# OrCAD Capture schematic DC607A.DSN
size Custom; title: LTC3722EGN-1, 36-72Vin to 12V/35A Isolated Supply; rev: A; company: LINEAR TECHNOLOGY; note: DC607A
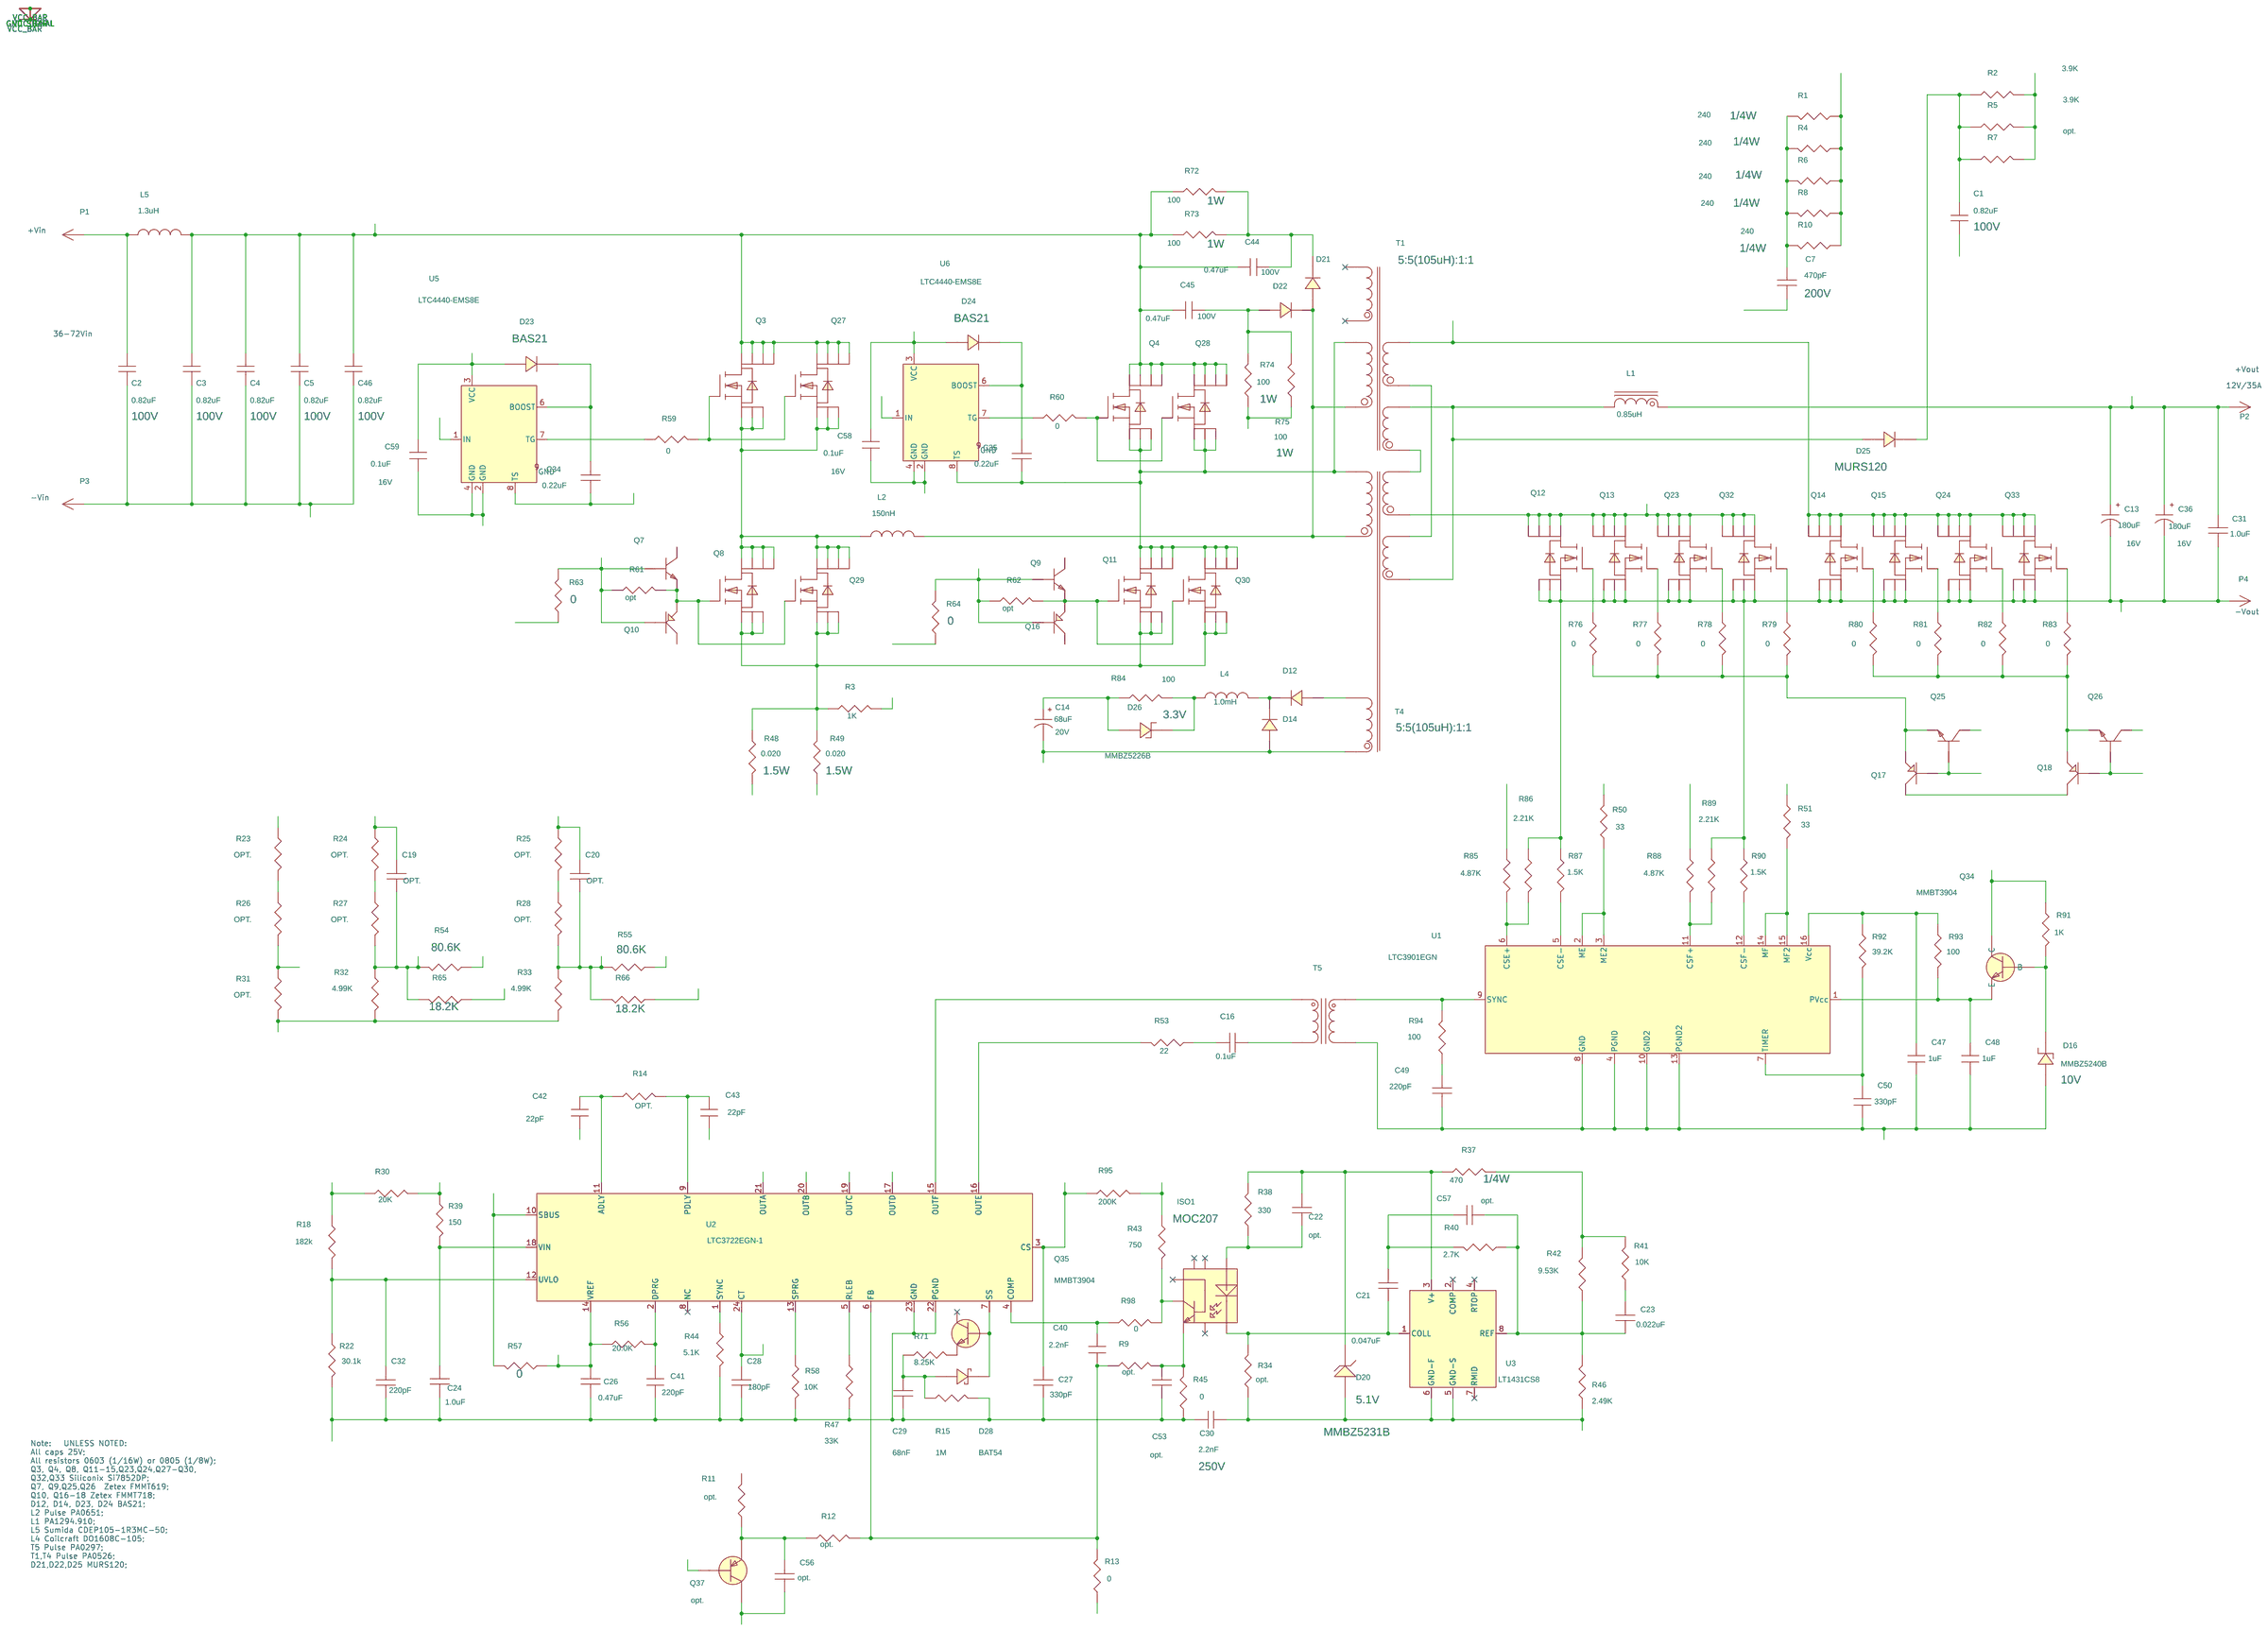
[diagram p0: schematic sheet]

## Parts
C1  0.82uF  [1812]
C2  0.82uF  [1812]
C3  0.82uF  [1812]
C4  0.82uF  [1812]
C5  0.82uF  [1812]
C7  470pF  [CAP1206]
C13  180uF  [CAP-OS-CON-E]
C14  68uF  [CAP7343]
C16  0.1uF  [CAP0805]
C19  OPT.  [CAP0805]
C20  OPT.  [CAP0805]
C21  0.047uF  [CAP0805]
C22  opt.  [CAP0805]
C23  0.022uF  [CAP0805]
C24  1.0uF  [CAP1206]
C26  0.47uF  [CAP1206]
C27  330pF  [CAP0805]
C28  180pF  [CAP0805]
C29  68nF  [CAP0805]
C30  2.2nF  [CAP-KH220]
C31  1.0uF  [CAP1206]
C32  220pF  [CAP0805]
C34  0.22uF  [CAP0805]
C35  0.22uF  [CAP0805]
C36  180uF  [CAP-OS-CON-E]
C40  2.2nF  [CAP0603]
C41  220pF  [CAP0603]
C42  22pF  [CAP0603]
C43  22pF  [CAP0603]
C44  0.47uF  [CAP1210]
C45  0.47uF  [CAP1210]
C46  0.82uF  [1812]
C47  1uF  [CAP0603]
C48  1uF  [CAP0603]
C49  220pF  [CAP0805]
C50  330pF  [CAP0603]
C53  opt.  [CAP0805]
C56  opt.  [CAP0805]
C57  opt.  [CAP0805]
C58  0.1uF  [CAP0603]
C59  0.1uF  [CAP0603]
D12  BAS21  [SOT23DIODE]
D14  BAS21  [SOT23DIODE]
D16  MMBZ5240B  [SOT23]
D20  MMBZ5231B  [SOT23DIODE]
D21  MBRS120T3  [SMB]
D22  MBRS120T3  [SMB]
D23  BAS21  [SOT23DIODE]
D24  BAS21  [SOT23DIODE]
D25  ES1G  [SMB]
D26  MMBZ5226B  [SOT23]
D28  BAT54  [SOT23]
ISO1  MOC207  [so8nb]
L1  0.85uH  [IND-PA1294/1494]
L2  150nH  [KM2T16AWG55041]
L4  1.0mH  [DO1608C]
L5  1.3uH  [IND-CDEP105]
P1  1455-2  [KEYSTONE-1455-2]
P2  1455-2  [KEYSTONE-1455-2]
P3  1455-2  [KEYSTONE-1455-2]
P4  1455-2  [KEYSTONE-1455-2]
Q3  Si7852DP  [POWERPAK-SO-8]
Q4  Si7852DP  [POWERPAK-SO-8]
Q7  FMMT619  [SOT23TRANS]
Q8  Si7852DP  [POWERPAK-SO-8]
Q9  FMMT619  [SOT23TRANS]
Q10  FMMT718  [SOT23TRANS]
Q11  Si7852DP  [POWERPAK-SO-8]
Q12  SI7456DP  [POWERPAK-SO-8]
Q13  SI7456DP  [POWERPAK-SO-8]
Q14  SI7456DP  [POWERPAK-SO-8]
Q15  SI7456DP  [POWERPAK-SO-8]
Q16  FMMT718  [SOT23TRANS]
Q17  FMMT718  [SOT23TRANS]
Q18  FMMT718  [SOT23TRANS]
Q23  SI7456DP  [POWERPAK-SO-8]
Q24  SI7456DP  [POWERPAK-SO-8]
Q25  FMMT619  [SOT23TRANS]
Q26  FMMT619  [SOT23TRANS]
Q27  Si7852DP  [POWERPAK-SO-8]
Q28  Si7852DP  [POWERPAK-SO-8]
Q29  Si7852DP  [POWERPAK-SO-8]
Q30  Si7852DP  [POWERPAK-SO-8]
Q32  (opt.)  [POWERPAK-SO-8]
Q33  (opt.)  [POWERPAK-SO-8]
Q34  MMBT3904  [SOT23]
Q35  MMBT3904  [SOT23]
Q37  opt.  [SOT23]
R1  240  [RES1206]
R2  3.9K  [RES1206]
R3  1K  [RES0603]
R4  240  [RES1206]
R5  3.9K  [RES1206]
R6  240  [RES1206]
R7  opt.  [RES1206]
R8  240  [RES1206]
R9  opt.  [RES0603]
R10  240  [RES1206]
R11  opt.  [RES0603]
R12  opt.  [RES0603]
R13  0  [RES0603]
R14  OPT.  [RES0603]
R15  1M  [RES0603]
R18  182k  [RES0805]
R22  30.1k  [RES0805]
R23  OPT.  [RES0805]
R24  OPT.  [RES0805]
R25  OPT.  [RES0805]
R26  OPT.  [RES0805]
R27  OPT.  [RES0805]
R28  OPT.  [RES0805]
R30  20K  [RES0805]
R31  OPT.  [RES0603]
R32  4.99K  [RES0603]
R33  4.99K  [RES0603]
R34  opt.  [RES0805]
R37  470  [RES1206]
R38  330  [RES0805]
R39  150  [RES0805]
R40  2.7K  [RES0805]
R41  10K  [RES0805]
R42  9.53K  [RES0805]
R43  750  [RES0603]
R44  5.1K  [RES0603]
R45  0  [RES0805]
R46  2.49K  [RES0805]
R47  33K  [RES0603]
R48  0.020  [2512]
R49  0.020  [2512]
R50  33  [RES0805]
R51  33  [RES0805]
R53  22  [RES0805]
R54  80.6K  [RES0603]
R55  80.6K  [RES0603]
R56  20.0K  [RES0603]
R57  0  [RES0603]
R58  10K  [RES0603]
R59  0  [RES0603]
R60  0  [RES0603]
R61  opt  [RES0603]
R62  opt  [RES0603]
R63  0  [RES0603]
R64  0  [RES0603]
R65  18.2K  [RES0603]
R66  18.2K  [RES0603]
R71  8.25K  [RES0603]
R72  100  [RES-LR2512]
R73  100  [RES-LR2512]
R74  100  [RES-LR2512]
R75  100  [RES-LR2512]
R76  0  [RES0603]
R77  0  [RES0603]
R78  0  [RES0603]
R79  0  [RES0603]
R80  0  [RES0603]
R81  0  [RES0603]
R82  0  [RES0603]
R83  0  [RES0603]
R84  100  [RES1206]
R85  4.87K  [RES1206]
R86  2.21K  [RES0603]
R87  1.5K  [RES0603]
R88  4.87K  [RES1206]
R89  2.21K  [RES0603]
R90  1.5K  [RES0603]
R91  1K  [RES0603]
R92  39.2K  [RES0603]
R93  100  [RES0603]
R94  100  [RES0805]
R95  200K  [RES0603]
R98  0  [RES0603]
T1  5:5(105uH):1:1  [TRANS-PA0526]
T4  5:5(105uH):1:1  [TRANS-PA0526]
T5  PA0297  [TRANS-PA0297]
U1  LTC3901EGN  [SSOP-16GN]
U2  LTC3722EGN-1  [SSOP-24GN]
U3  LT1431CS8  [SO-08]
U5  LTC4440-EMS8E  [msop08/cp]
U6  LTC4440-EMS8E  [msop08/cp]

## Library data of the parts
C1-C5 C46 = VJ1825Y155MXB: 1ST PART FIELD: 100V; 2ND PART FIELD: 20%, 1812; 3RD PART FIELD: X7R; 4TH PART FIELD: VITRAMON; 5TH PART FIELD: VJ1812Y824KXBAT; 7TH PART FIELD: CAP.
C7 = 12061C104KAT2A_0: 1ST PART FIELD: 200V; 2ND PART FIELD: 10%, 1206; 3RD PART FIELD: NPO; 4TH PART FIELD: AVX; 5TH PART FIELD: 12062A471KAT2A; 7TH PART FIELD: CAP.
C13 C36 = CAP-OS-CON-E: 1ST PART FIELD: 16V
C14 = CAP+7343: 1ST PART FIELD: 20V
C16 C21 C22 C34 C35 C49 C57 = 12061C104KAT2A_0: 1ST PART FIELD: 25V; 2ND PART FIELD: 10%, 0805; 3RD PART FIELD: X7R; 4TH PART FIELD: AVX; 5TH PART FIELD: 08053C104KAT2A; 7TH PART FIELD: CAP.
C19 C20 = 12061C104KAT2A_0: 1ST PART FIELD: 100V; 2ND PART FIELD: 10%, 0805; 3RD PART FIELD: NPO; 4TH PART FIELD: AVX; 5TH PART FIELD: 08052A4R7KAT2A; 7TH PART FIELD: CAP.
C23 = 12061C104KAT2A_0: 1ST PART FIELD: 25V; 2ND PART FIELD: 10%, 0805; 3RD PART FIELD: X7R; 4TH PART FIELD: AVX; 5TH PART FIELD: 08053C223KAT2A; 7TH PART FIELD: CAP.
C24 C26 C31 = TMK316BJ105KL: 1ST PART FIELD: 25V; 2ND PART FIELD: 10%, 1206; 3RD PART FIELD: X7R; 4TH PART FIELD: TAIYO TUDEN; 7TH PART FIELD: CAP.
C27 C53 = 12061C104KAT2A_0: 1ST PART FIELD: 25V; 2ND PART FIELD: 10%, 0805; 3RD PART FIELD: NPO; 4TH PART FIELD: AVX; 5TH PART FIELD: 08053A331KAT2A; 7TH PART FIELD: CAP.
C28 C56 = 12061C104KAT2A_0: 1ST PART FIELD: 25V; 2ND PART FIELD: 10%, 0805; 3RD PART FIELD: NPO; 4TH PART FIELD: AVX; 5TH PART FIELD: 08053A151KAT2A; 7TH PART FIELD: CAP.
C29 = 12061C104KAT2A_0: 1ST PART FIELD: 25V; 2ND PART FIELD: 10%, 0805; 3RD PART FIELD: X7R; 4TH PART FIELD: AVX; 5TH PART FIELD: 08053C683KAT2A; 7TH PART FIELD: CAP.
C30 = GHM3045X7R222K-GC: 1ST PART FIELD: 250V; 2ND PART FIELD: 10%, GHM3045; 3RD PART FIELD: X7R; 4TH PART FIELD: MURATA ERIE; 7TH PART FIELD: CAP.
C32 = 12061C104KAT2A_0: 1ST PART FIELD: 25V; 2ND PART FIELD: 10%, 0805; 3RD PART FIELD: NPO; 4TH PART FIELD: AVX; 5TH PART FIELD: 08053A101KAT2A; 7TH PART FIELD: CAP.
C40-C43 C47 C48 C50 = CAP0603
C44 C45 = CAP1210: 1ST PART FIELD: 100V
C58 C59 = CAP0603: 1ST PART FIELD: 16V
D12 D14 D23 D24 = BAS21LT1: 1ST PART FIELD: 200V; 2ND PART FIELD: SOT23; 3RD PART FIELD: FAST SWITCHING; 4TH PART FIELD: DIODES INC.; 7TH PART FIELD: DIODE
D16 = MMBZ5221B-5259B: V: 10V
D20 = MMBZ5248BLT1_0: 1ST PART FIELD: 5.1V; 2ND PART FIELD: 5%, SOT23; 3RD PART FIELD: ZENER; 4TH PART FIELD: DIODES INC.; 5TH PART FIELD: MMBZ5240B-7; 7TH PART FIELD: DIODE
D21 D22 = MBRS120T3: 1ST PART FIELD: 200V; 3RD PART FIELD: SUPER FAST; 4TH PART FIELD: DIODES INC.; 5TH PART FIELD: MBRS120
D25 = MBRS120T3: 1ST PART FIELD: 200V; 3RD PART FIELD: SUPER FAST; 4TH PART FIELD: DIODES INC.; 5TH PART FIELD: MURS120
D26 = MMBZ5221B-5259B: v: 3.3V
D28 = BAT54
ISO1 = MOC207: 1ST PART FIELD: 3000VAC; 2ND PART FIELD: SO8; 3RD PART FIELD: OPTOISOLATOR; 4TH PART FIELD: FAIRCHILD SEMI.; 7TH PART FIELD: I.C.
L1 = IND-PA1494-PULSE_3
L2 = DO1608C-105: 3RD PART FIELD: POWDER TORROID; 4TH PART FIELD: PULSE; 5TH PART FIELD: PA0573 (8T19AWGT44-2); 7TH PART FIELD: INDUCTOR
L4 = DO1608C-105: 3RD PART FIELD: FERRITE DRUM; 4TH PART FIELD: COILCRAFT; 7TH PART FIELD: INDUCTOR
L5 = DO1608C-105: 3RD PART FIELD: FERRITE; 4TH PART FIELD: SUMIDA; 5TH PART FIELD: CDEP105-1R3MC-50; 7TH PART FIELD: INDUCTOR
P1-P4 = Keystone-1455-2: 3RD PART FIELD: PIN 0.08 SWAGE MOUNT; 4TH PART FIELD: KEYSTONE; 7TH PART FIELD: CONNECTOR
Q3 Q4 Q8 Q11-Q15 Q23 Q24 Q27-Q30 Q32 Q33 = SI7456DP: 2ND PART FIELD: POWERPAK SO-8; 3RD PART FIELD: N-CHANNEL; 7TH PART FIELD: FET
Q7 Q9 = KM_NPN_0: 2ND PART FIELD: SOT23; 3RD PART FIELD: NPN; 4TH PART FIELD: ZETEX; 7TH PART FIELD: XSTR.
Q10 = MMBT3906LT1_3: 2ND PART FIELD: SOT23; 3RD PART FIELD: PNP; 4TH PART FIELD: ZETEX; 7TH PART FIELD: XSTR.
Q16 = MMBT3906LT1_2: 2ND PART FIELD: SOT23; 3RD PART FIELD: PNP; 4TH PART FIELD: ZETEX; 7TH PART FIELD: XSTR.
Q17 = MMBT3906LT1_1: 2ND PART FIELD: SOT23; 3RD PART FIELD: PNP; 4TH PART FIELD: ZETEX; 7TH PART FIELD: XSTR.
Q18 = MMBT3906LT1: 2ND PART FIELD: SOT23; 3RD PART FIELD: PNP; 4TH PART FIELD: ZETEX; 7TH PART FIELD: XSTR.
Q25 Q26 = KM_NPN_0: 2ND PART FIELD: SOT23; 3RD PART FIELD: NPN; 7TH PART FIELD: XSTR.
Q34 = MMBT3904
Q35 = MMBT3904_1
Q37 = MMBT3906_0
R1 R4 R6 R8 R10 = CR18-274JM: 1ST PART FIELD: 1/4W; 2ND PART FIELD: 5%, 1206; 3RD PART FIELD: CHIP; 4TH PART FIELD: AAC; 5TH PART FIELD: CR18-241JM; 7TH PART FIELD: RES.
R2 R5 R7 = AAC-1206: 2ND PART FIELD: 5%, 1206; 5TH PART FIELD: CR18-913JM; 7TH PART FIELD: RES.
R3 = CR10-203JM_0: 1ST PART FIELD: 1/16W; 2ND PART FIELD: 5%, 0603; 3RD PART FIELD: CHIP; 4TH PART FIELD: AAC; 5TH PART FIELD: CR16-102JM; 7TH PART FIELD: RES.
R9 R11-R14 R43 R76-R83 R86 R87 R89-R93 R95 R98 = AAC-0603
R15 R47 R71 = CR10-203JM_0: 1ST PART FIELD: 1/16W; 2ND PART FIELD: 5%, 0603; 3RD PART FIELD: CHIP; 4TH PART FIELD: AAC; 5TH PART FIELD: CR16-333JM; 7TH PART FIELD: RES.
R18 = AAC-0805: 2ND PART FIELD: 5%, 0805; 5TH PART FIELD: CR10-184JM; 7TH PART FIELD: RES.
R22 = AAC-0805: 2ND PART FIELD: 5%, 0805; 5TH PART FIELD: CR10-303JM; 7TH PART FIELD: RES.
R23 R26 = CR10-203JM_0: 1ST PART FIELD: 1/8W; 2ND PART FIELD: 1%, 0805; 3RD PART FIELD: CHIP; 4TH PART FIELD: AAC; 5TH PART FIELD: CR10-1542FM; 7TH PART FIELD: RES.
R24 R25 R27 R28 = CR10-203JM_0: 1ST PART FIELD: 1/8W; 2ND PART FIELD: 1%, 0805; 3RD PART FIELD: CHIP; 4TH PART FIELD: AAC; 5TH PART FIELD: CR10-1332FM; 7TH PART FIELD: RES.
R30 = CR10-203JM_0: 1ST PART FIELD: 1/8W; 2ND PART FIELD: 5%, 0805; 3RD PART FIELD: CHIP; 4TH PART FIELD: AAC; 5TH PART FIELD: CR10-153JM; 7TH PART FIELD: RES.
R31-R33 = CR10-203JM_0: 1ST PART FIELD: 1/16W; 2ND PART FIELD: 1%, 0603; 3RD PART FIELD: CHIP; 4TH PART FIELD: AAC; 5TH PART FIELD: CR16-1001FM; 7TH PART FIELD: RES.
R34 R45 = CR10-203JM_0: 1ST PART FIELD: 1/8W; 2ND PART FIELD: 5%, 0805; 3RD PART FIELD: CHIP; 4TH PART FIELD: AAC; 5TH PART FIELD: CR10-104JM; 7TH PART FIELD: RES.
R37 = CR18-274JM: 1ST PART FIELD: 1/4W; 2ND PART FIELD: 5%, 1206; 3RD PART FIELD: CHIP; 4TH PART FIELD: AAC; 5TH PART FIELD: CR18-201JM; 7TH PART FIELD: RES.
R38 = CR10-203JM_0: 1ST PART FIELD: 1/8W; 2ND PART FIELD: 5%, 0805; 3RD PART FIELD: CHIP; 4TH PART FIELD: AAC; 5TH PART FIELD: CR10-471JM; 7TH PART FIELD: RES.
R39 = AAC-0805
R40 = CR10-203JM_0: 1ST PART FIELD: 1/8W; 2ND PART FIELD: 5%, 0805; 3RD PART FIELD: CHIP; 4TH PART FIELD: AAC; 5TH PART FIELD: CR10-102JM; 7TH PART FIELD: RES.
R41 = CR10-203JM_0: 1ST PART FIELD: 1/8W; 2ND PART FIELD: 5%, 0805; 3RD PART FIELD: CHIP; 4TH PART FIELD: AAC; 5TH PART FIELD: CR10-103JM; 7TH PART FIELD: RES.
R42 R94 = CR10-203JM_0: 1ST PART FIELD: 1/8W; 2ND PART FIELD: 1%, 0805; 3RD PART FIELD: CHIP; 4TH PART FIELD: AAC; 5TH PART FIELD: CR10-9531FM; 7TH PART FIELD: RES.
R44 = CR10-203JM_0: 1ST PART FIELD: 1/16W; 2ND PART FIELD: 5%, 0603; 3RD PART FIELD: CHIP; 4TH PART FIELD: AAC; 5TH PART FIELD: CR16-512JM; 7TH PART FIELD: RES.
R46 = CR10-203JM_0: 1ST PART FIELD: 1/8W; 2ND PART FIELD: 1%, 0805; 3RD PART FIELD: CHIP; 4TH PART FIELD: AAC; 5TH PART FIELD: CR10-2491FM; 7TH PART FIELD: RES.
R48 R49 = CR18-274JM: 1ST PART FIELD: 1.5W; 2ND PART FIELD: 2%, 2512; 3RD PART FIELD: CHIP; 4TH PART FIELD: IRC; 5TH PART FIELD: LRC-LR2512-01-R056-G; 7TH PART FIELD: RES.
R50 R51 = AAC-0805: 2ND PART FIELD: 0805; 5TH PART FIELD: CR10-000M; 7TH PART FIELD: RES.
R53 = CR10-203JM_0: 1ST PART FIELD: 1/8W; 2ND PART FIELD: 5%, 0805; 3RD PART FIELD: CHIP; 4TH PART FIELD: AAC; 5TH PART FIELD: CR10-220JM; 7TH PART FIELD: RES.
R54 R55 R57 R65 R66 = AAC-0805: 1ST PART FIELD: 1/16W; 2ND PART FIELD: 5%, 0603; 5TH PART FIELD: CR16-xxxJM; 7TH PART FIELD: RES.
R56 R58 = AAC-0805: 1ST PART FIELD: 1/16W; 2ND PART FIELD: 5%, 0603; 5TH PART FIELD: CR16-102JM; 7TH PART FIELD: RES.
R59-R64 = CR10-203JM_0: 1ST PART FIELD: 1/16W; 2ND PART FIELD: 0603; 3RD PART FIELD: CHIP; 4TH PART FIELD: AAC; 5TH PART FIELD: CR06-000M; 7TH PART FIELD: RES.
R72-R75 = LR-2512: 1ST PART FIELD: 1W
R84 R85 R88 = AAC-1206
T1 = TRANS-PB2001_5: 2ND PART FIELD: 1500VDC BA; 3RD PART FIELD: EI25/19 PLANAR; 4TH PART FIELD: PULSE; 5TH PART FIELD: PA0526; 7TH PART FIELD: TRANSFORMER
T4 = TRANS-PB2001_4: 2ND PART FIELD: 1500VDC BA; 3RD PART FIELD: EI25/19 PLANAR; 4TH PART FIELD: PULSE; 5TH PART FIELD: PA0526; 7TH PART FIELD: TRANSFORMER
T5 = TRANS-PA0297
U1 = LTC3901EGN_0
U2 = LT1339_29: 3RD PART FIELD: ANALOG; 4TH PART FIELD: LINEAR TECH.; 7TH PART FIELD: I.C.
U3 = LT1431: 2ND PART FIELD: SO8; 3RD PART FIELD: ANALOG; 4TH PART FIELD: LINEAR TECH.; 7TH PART FIELD: I.C.
U5 U6 = LT1693-1A_0: 2ND PART FIELD: MSOP; 3RD PART FIELD: ANALOG; 4TH PART FIELD: LINEAR TECH.; 7TH PART FIELD: I.C.

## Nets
5VREF: C26.1 R11.2 R43.1 R54.1 R55.1 R56.1 R57.1 R95.2 U2.14(VREF)
12V: C14.1 C58.1 C59.1 D23.A D24.A D26.1(ANODE) Q7.C Q9.C R30.1 R39.1 R84.1 U5.3(VCC) U6.3(VCC)
GND: C2.2 C3.2 C4.2 C5.2 C14.2 C24.2 C26.2 C27.2 C28.2 C29.2 C30.2 C32.2 C41.2 C42.1 C43.1 C46.2 C53.2 C56.2 C58.2 C59.2 D14.A P3.1 Q10.C Q16.C Q37.3(C) R13.1 R15.1 R22.2 R31.1 R32.1 R33.1 R44.1 R45.2 R47.1 R48.1 R49.1 R58.2 R74.1 R75.1 T4.1 U2.22(PGND) U2.23(GND) U5.2(GND) U5.4(GND) U5.9(GND) U6.2(GND) U6.4(GND) U6.9(GND)
VIN: C3.1 C4.1 C5.1 C44.1 C45.1 C46.1 L5.2 Q3.5 Q3.6 Q3.7 Q3.8 Q4.5 Q4.6 Q4.7 Q4.8 Q27.5 Q27.6 Q27.7 Q27.8 Q28.5 Q28.6 Q28.7 Q28.8 R18.1 R23.2 R30.2 R72.1 R73.1
+VOUT: C13.1 C31.1 C36.1 L1.1 L1.2(+VOUT) P2.1 Q25.C Q26.C Q34.3(C) R2.2 R5.2 R7.2 R37.2 R41.1 R42.1 R91.1
-VOUT: C1.2 C13.2 C30.1 C31.2 C36.2 C47.2 C48.2 C49.1 C50.2 D16.1(ANODE) D20.A P4.1 Q12.1 Q12.2 Q12.3 Q13.1 Q13.2 Q13.3 Q14.1 Q14.2 Q14.3 Q15.1 Q15.2 Q15.3 Q17.C Q18.C Q23.1 Q23.2 Q23.3 Q24.1 Q24.2 Q24.3 Q32.1 Q32.2 Q32.3 Q33.1 Q33.2 Q33.3 R34.2 R46.2 R86.1 R87.1 R89.1 R90.1 T5.5 U1.4(PGND) U1.8(GND) U1.10(GND2) U1.13(PGND2) U3.5(GND-S) U3.6(GND-F)
A: U2.21(OUTA) U5.1(IN)
A_LEG: C19.1 C35.2 Q4.1 Q4.2 Q4.3 Q11.5 Q11.6 Q11.7 Q11.8 Q28.1 Q28.2 Q28.3 Q30.5 Q30.6 Q30.7 Q30.8 R24.2 T1.4 T4.4 U6.8(TS)
ADLY: C19.2 C42.2 R14.1 R27.1 R32.2 R54.2 R65.2 U2.11(ADLY)
B: R63.2 R65.1 U2.20(OUTB)
C: R66.1 U2.19(OUTC) U6.1(IN)
CT: C28.1 Q37.1(B) U2.24(CT)
D: R64.2 U2.17(OUTD)
ISNS: C27.1 R3.2 R95.1 U2.3(CS)
MB: Q7.B Q10.B R61.2 R63.1
MD: Q9.B Q16.B R62.2 R64.1
ME: Q17.B Q25.B R50.2
MF: Q18.B Q26.B R51.1
P_LEG: C20.1 C34.2 L2.1 Q3.1 Q3.2 Q3.3 Q8.5 Q8.6 Q8.7 Q8.8 Q27.1 Q27.2 Q27.3 Q29.5 Q29.6 Q29.7 Q29.8 R25.2 U5.8(TS)
PDLY: C20.2 C43.2 R14.2 R28.1 R33.2 R55.2 R66.2 U2.9(PDLY)
SBUS: R26.1 R31.2 R57.2 U2.10(SBUS)
VHIGH: C7.1 Q12.5 Q12.6 Q12.7 Q12.8 Q13.5 Q13.6 Q13.7 Q13.8 Q23.5 Q23.6 Q23.7 Q23.8 Q32.5 Q32.6 Q32.7 Q32.8 R85.1 T4.10
VLOW: Q14.5 Q14.6 Q14.7 Q14.8 Q15.5 Q15.6 Q15.7 Q15.8 Q24.5 Q24.6 Q24.7 Q24.8 Q33.5 Q33.6 Q33.7 Q33.8 R1.1 R4.1 R6.1 R8.1 R10.1 R88.1 T1.11
N137681: C22.1 D20.K R37.1 R38.1 U3.3(V+)
N549607: C23.2 C57.2 R40.2 R42.2 R46.1 U3.8(REF)
N549645: C21.2 ISO1.2 R34.1 U3.1(COLL)
N608189: C2.1 L5.1 P1.1
N623445: Q8.1 Q8.2 Q8.3 Q11.1 Q11.2 Q11.3 Q29.1 Q29.2 Q29.3 Q30.1 Q30.2 Q30.3 R3.1 R48.2 R49.2
N628690: Q7.E Q8.4 Q10.E Q29.4 R61.1
N630834: Q9.E Q11.4 Q16.E Q30.4 R62.1
N633500: D12.K D14.K L4.2
N643451: R23.1 R26.2
N645124: R24.1 R27.2
N645174: R25.1 R28.2
N658044: C7.2 R1.2 R4.2 R6.2 R8.2 R10.2
N694250: D12.A T4.6
N740313: Q3.4 Q27.4 R59.1
N740447: Q4.4 Q28.4 R60.1
N741488: D21.2 D22.1 L2.2 T1.2 T4.2
N743526: T5.1 U2.15(OUTF)
N743538: R53.1 U2.16(OUTE)
N760104: C16.2 T5.8
N779960: C32.1 R18.2 R22.1 U2.12(UVLO)
N780592: C16.1 R53.2
N782467: ISO1.6 R43.2 R98.2
N783687: C24.1 R39.2 U2.18(VIN)
N784296: D28.3 Q35.1(B) U2.7(SS)
N784515: R47.2 U2.5(RLEB)
N784518: R58.1 U2.13(SPRG)
N785233: C41.1 R56.2 U2.2(DPRG)
N786417: R44.2 U2.1(SYNC)
N800276: C1.1 D25.1 R2.1 R5.1 R7.1
N16676398: R59.2 U5.7(TG)
N16676409: C34.1 D23.K U5.6(BOOST)
N16679583: C35.1 D24.K U6.6(BOOST)
N16704058: T1.7 T4.11
N16704514: D25.2 L1.4(N16704514) L1.5 T1.8 T4.7
N16704583: T1.10 T4.8
N16749879: C44.2 D21.1 R72.2 R73.2
N16751043: C45.2 D22.2 R74.2 R75.2
N16757519: D26.3(CATHODE) L4.1 R84.2
N16759774: C53.1 ISO1.5 R9.2 R45.1
N16764312: C40.1 R98.1 U2.4(COMP)
N16769258: C40.2 R9.1 R12.2 R13.2 U2.6(FB)
N16770158: C29.1 D28.1 R15.2 R71.2
N16772701: C56.1 Q37.2(E) R11.1 R12.1
N16781315: R94.1 T5.4 U1.9(SYNC)
N16782755: C49.2 R94.2
N16783562: C50.1 R92.2 U1.7(TIMER)
N16784041: C47.1 R92.1 R93.1 U1.16(Vcc)
N16784122: C48.1 Q34.2(E) R93.2 U1.1(PVcc)
N16784623: D16.3(CATHODE) Q34.1(B) R91.2
N16785371: R85.2 R86.2 U1.6(CSE+)
N16791213: Q35.2(E) R71.1
N16797207: Q18.E Q26.E R80.2 R81.2 R82.2 R83.2
N16797220: Q17.E Q25.E R76.2 R77.2 R78.2 R79.2
N16797786: Q12.4 R76.1
N16797805: Q13.4 R77.1
N16797824: Q23.4 R78.1
N16797843: Q32.4 R79.1
N16797910: Q33.4 R83.1
N16797929: Q24.4 R82.1
N16797948: Q15.4 R81.1
N16797967: Q14.4 R80.1
N16799458: R87.2 U1.5(CSE-)
N16799775: R50.1 U1.2(ME) U1.3(ME2)
N16801262: R88.2 R89.2 U1.11(CSF+)
N16801326: R90.2 U1.12(CSF-)
N16801581: R51.2 U1.14(MF) U1.15(MF2)
N16805690: R60.2 U6.7(TG)
N16816581: C23.1 R41.2
N16818558: C22.2 ISO1.1 R38.2
N16824353: C21.1 C57.1 R40.1

Not connected (* = marked no-connect by the designer): ISO1 3* 4* 7* 8*; Q35 3(C)*; T1 1* 6*; U2 8(NC)*; U3 2(COMP)* 4(RTOP)* 7(RMID)*

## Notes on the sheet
- +Vin
- 36-72Vin
- +Vout
- 12V/35A
- -Vin
- -Vout
- Note:   UNLESS NOTED:
  All caps 25V;
  All resistors 0603 (1/16W) or 0805 (1/8W);
  Q3, Q4, Q8, Q11-15,Q23,Q24,Q27-Q30,
  Q32,Q33 Siliconix Si7852DP;
  Q7, Q9,Q25,Q26  Zetex FMMT619;
  Q10, Q16-18 Zetex FMMT718;
  D12, D14, D23, D24 BAS21;
  L2 Pulse PA0651;
  L1 PA1294.910;
  L5 Sumida CDEP105-1R3MC-50;
  L4 Coilcraft DO1608C-105;
  T5 Pulse PA0297;
  T1,T4 Pulse PA0526;
  D21,D22,D25 MURS120;
